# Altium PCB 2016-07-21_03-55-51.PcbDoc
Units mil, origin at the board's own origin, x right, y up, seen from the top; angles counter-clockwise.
Board outline 4250 x 2000 mil, 4 copper layers (Top Layer, MidLayer1, MidLayer2, Bottom Layer); 25 components, 16 nets, 65 pads, 67 vias.
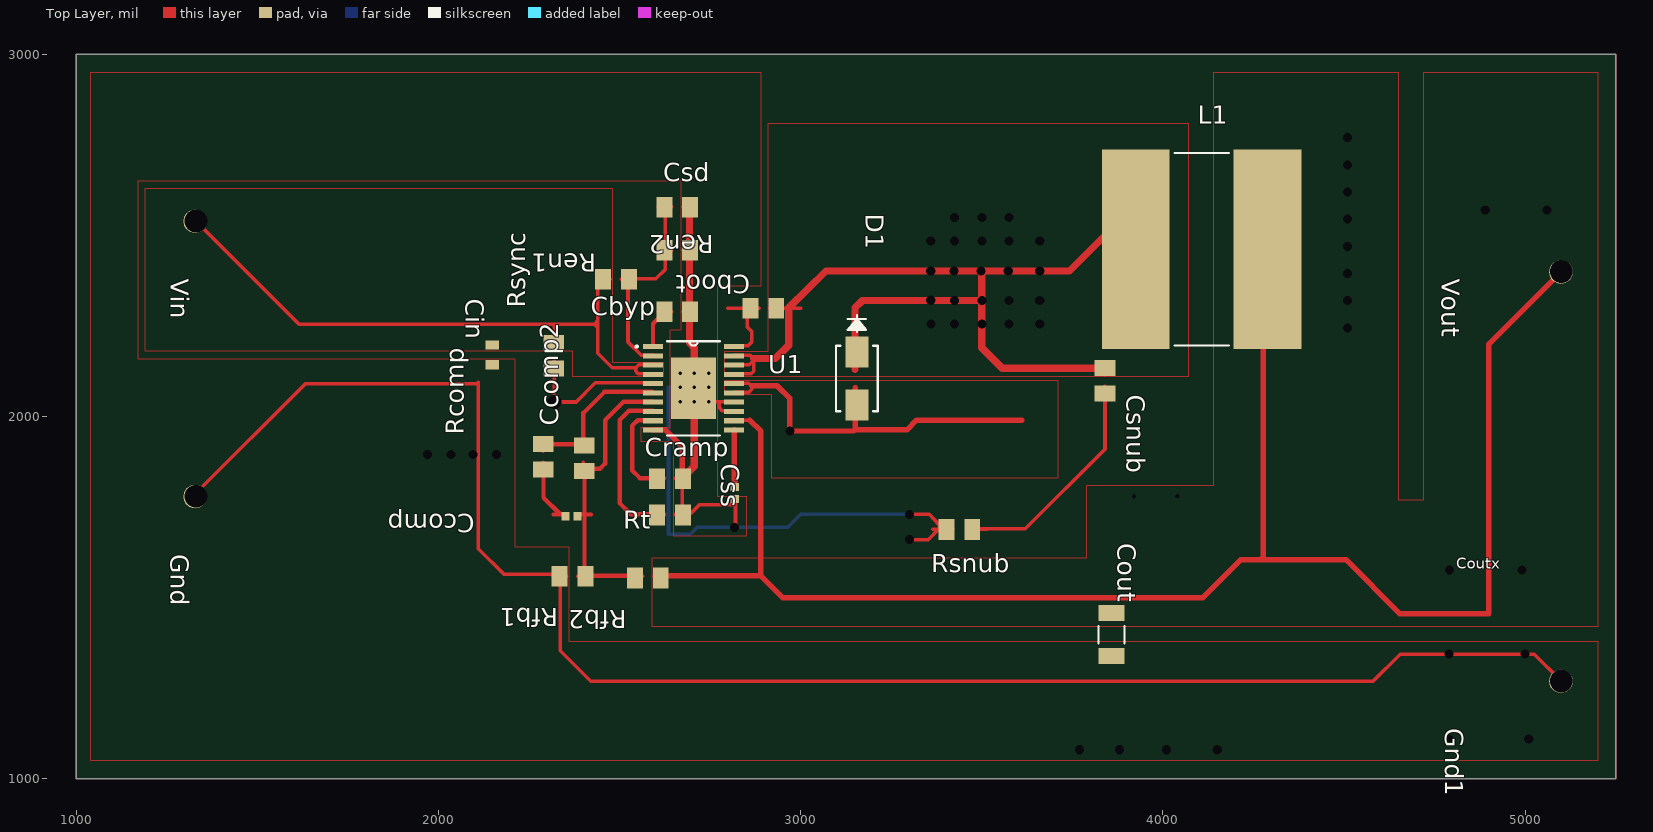
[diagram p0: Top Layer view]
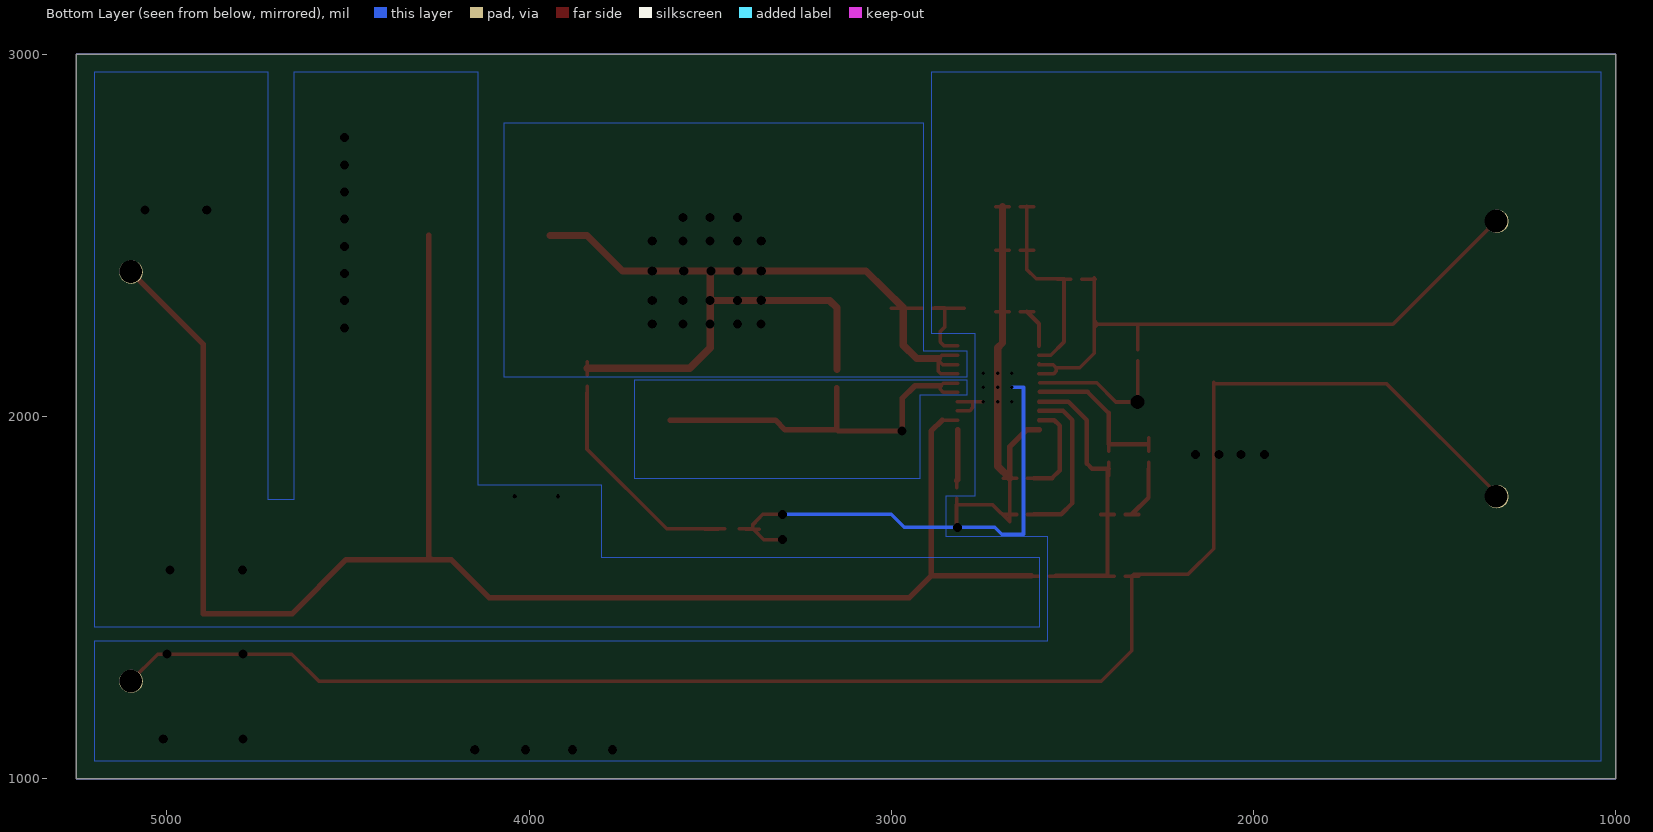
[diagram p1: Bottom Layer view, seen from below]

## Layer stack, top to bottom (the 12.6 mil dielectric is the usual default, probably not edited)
Top Layer: signal copper 1.4
Dielectric: core 12.6, FR-4, Dk 4.8
MidLayer1: signal copper 1.4
Dielectric: prepreg 12.6, FR-4, Dk 4.8
MidLayer2: signal copper 1.4
Dielectric: core 12.6, FR-4, Dk 4.8
Bottom Layer: signal copper 1.4

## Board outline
1000,1000 5250,1000 5250,3000 1000,3000

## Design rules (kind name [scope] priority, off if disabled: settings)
PlaneConnect [All] p0: scope1count=1 scope1_0_kind=Board scope1_0_value=Board scope2count=1 scope2_0_kind=Board scope2_0_value=Board commentlength=0 planeconnectstyle=Direct reliefexpansion=20 reliefentries=4 reliefconductorwidth=10 reliefairgap=10
PlaneConnect [All] p1: planeconnectstyle=Direct reliefexpansion=20 reliefentries=4 reliefconductorwidth=10 reliefairgap=10
PolygonConnect [All] p0: scope1count=1 scope1_0_kind=Board scope1_0_value=Board scope2count=1 scope2_0_kind=Board scope2_0_value=Board commentlength=0 connectstyle=Direct reliefconductorwidth=10 reliefentries=4 polygonreliefangle="90 Angle"
PolygonConnect [All] p1: connectstyle=Direct reliefconductorwidth=10 reliefentries=4 polygonreliefangle="90 Angle"

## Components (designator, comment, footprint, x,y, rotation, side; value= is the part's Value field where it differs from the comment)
Cboot "" 0805 2897,2299 r180 top
Cbyp "" 0805 2659,2289 r0 top
Ccomp "" 0402 2367,1725 r180 top
Ccomp2 "" 0805 2402,1885 r90 top
Cin "" 0603 2148,2170 r270 top
Cout "" 1206_190 3858,1398 r270 top
Cramp "" 0805 2639,1828 r0 top
Csd "" 0805 2659,2578 r0 top
Csnub "" 0805 3840,2099 r270 top
Css "" 0402 2818,1789 r270 top
D1 "" SMA 3155,2105 r270 top
Gnd "" TP-1502 1328,1779 r270 top
Gnd1 "" TP-1502 5099,1269 r270 top
L1 "" SDR1307 4107,2462 r0 top
Rcomp "" 0805 2289,1889 r90 top
Ren1 "" 0805 2490,2379 r180 top
Ren2 "" 0805 2659,2459 r180 top
Rfb1 "" 0805 2370,1559 r180 top
Rfb2 "" 0805 2578,1554 r180 top
Rsnub "" 0805 3438,1688 r0 top
Rsync "" 0805 2318,2168 r90 top
Rt "" 0805 2639,1728 r0 top
U1 "" MXA20A 2704,2078 r0 top
Vin "" TP-1502 1328,2539 r270 top
Vout "" TP-1502 5099,2399 r270 top

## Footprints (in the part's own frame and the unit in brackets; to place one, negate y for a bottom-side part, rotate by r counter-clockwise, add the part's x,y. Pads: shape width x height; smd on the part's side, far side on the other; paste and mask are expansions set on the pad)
0402 [mil]
  rect 22x24 smd: 1(-16.5,0) 2(16.5,0)
0603 [mil]
  rect 26x38 smd: 1(-27.5,0) 2(27.5,0)
0805 [mil]
  rect 44x57 smd: 1(-35.5,0) 2(35.5,0)
1206_190 [mil]
  rect 44x71 smd: 1(-59,0) 2(59,0)
  silkscreen extent -24,-36 24,36
MXA20A [mil]
  rect 56x14 smd: 1(-112,115.16) 2(-112,89.57) 3(-112,63.98) 4(-112,38.39) 5(-112,12.8) 6(-112,-12.8) 7(-112,-38.39) 8(-112,-63.98) 9(-112,-89.57) 10(-112,-115.16) 11(112,-115.16) 12(112,-89.57) 13(112,-63.98) 14(112,-38.39) 15(112,-12.8) 16(112,12.8) 17(112,38.39) 18(112,63.98) 19(112,89.57) 20(112,115.16)
  rect 124x171 smd: 21(0,0)
  silkscreen extent -160,-130 74,130
SDR1307 [mil]
  rect 187x551 smd: 1(-182,0) 2(182,0)
  silkscreen extent -75,-266 75,266
SMA [mil]
  rect 86x64 smd: 1(-73,0) 2(73,0)
  silkscreen extent -174,-58 91,58
TP-1502 [mil]
  round 65 / inner round 0 / far side round 65 hole 32: 1(0,0)

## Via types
v1: diameter 0, hole 25, Top Layer to Bottom Layer, 51 vias
v2: diameter 0, hole 10, Top Layer to Bottom Layer, 9 vias
v3: diameter 0, hole 63, Top Layer to Bottom Layer, 4 vias
v4: diameter 0, hole 12, Top Layer to Bottom Layer, 2 vias
v5: diameter 0, hole 38, Top Layer to Bottom Layer, 1 vias

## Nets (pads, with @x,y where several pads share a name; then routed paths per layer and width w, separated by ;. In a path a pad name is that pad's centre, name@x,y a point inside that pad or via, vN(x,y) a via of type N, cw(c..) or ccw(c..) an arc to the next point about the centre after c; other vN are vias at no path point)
0: Cbyp.2 Cin.2 Cout.2 Cramp.2 Csd.2 Css.2 Gnd1.1 Gnd.1 Ren2.1 Rfb1.2 Rsnub.1 Rt.2 U1.10 U1.13 U1.14 U1.21 | length 7788.8
  Top Layer w10: v3(1330,1780) 1330,1788 1632,2090 2105,2090 2110,2094 2110,1635 2180,1565 Rfb1.2@2331,1565 ; Rfb1.2@2317,1559.5 Rfb1.2@2354,1559.5 ; Rfb1.2@2336,1560 2336,1353 2420,1269 4580,1269 4655,1344 v1(4790,1344) 4900,1344 5025,1344 v3(5100,1270) ; Rt.2@2654,1729.5 Rt.2@2691,1729.5 ; Cramp.2@2654,1829.5 Cramp.2@2691,1829.5 ; Cramp.2@2673,1830 2673,1710 2720,1756 2820,1756 2820,1697 v1(2817,1694) ; Cbyp.2@2674,2289.5 Cbyp.2@2711,2289.5 ; Ren2.1@2674,2459.5 Ren2.1@2711,2459.5 ; Csd.2@2674,2579.5 Csd.2@2711,2579.5 ; v2(2746,2041) 2775,2041 ; U1.13@2817,2016 2783,2016 2775,2025 2775,2041 ; U1.14@2817,2041 2775,2041 ; 2819.5,1737 Css.2@2819.5,1774 ; v1(3300,1660) 3352,1660 Rsnub.1@3382,1690 ; v1(3300,1730) 3355,1730 3382,1702 Rsnub.1@3382,1690 ; 3364,1689 Rsnub.1@3401,1689 ; Rsnub.1@3420,1690 Rsnub.1@3382,1690
  Top Layer w15: U1.10@2592,1964 2625,1964 2673,1916 Cramp.2@2673,1830
  Top Layer w20: Cramp.2@2673,1830 2706,1863 v2(2706,2041) v2(2706,2081) v2(2706,2120) 2706,2190 2693,2203 2693,2290 2693,2460 Csd.2@2693,2580
  Bottom Layer w10: v2(2667,2081) 2635,2081 2635,1675 2695,1675 2714,1694 v1(2817,1694) 2964,1694 3000,1730 v1(3300,1730)
  other v1: 3770,1080 3880,1080 4010,1080 4150,1080 4790,1110 5010,1110 5000,1344 1970,1895 2035,1895 2095,1895 2160,1895
  other v2: 2667,2041 2746,2081 2667,2120 2746,2120
1: Css.1 U1.11 | length 179.2
  Top Layer w10: Css.1@2819.5,1804 2819.5,1841
  Top Layer w15: U1.11@2817,1964 2817,1826 2820,1823
2: Cbyp.1 U1.1 | length 146.1
  Top Layer w10: Cbyp.1@2607,2289.5 Cbyp.1@2644,2289.5
  Top Layer w12: U1.1@2592,2195 2592,2256 Cbyp.1@2626,2290
3: Cramp.1 U1.9 | length 303.9
  Top Layer w10: Cramp.1@2587,1829.5 Cramp.1@2624,1829.5
  Top Layer w12: U1.9@2592,1990 2550,1990 2535,1975 2535,1851 2556,1830 Cramp.1@2606,1830
4: Rt.1 U1.8 | length 487.6
  Top Layer w10: Rt.1@2587,1729.5 Rt.1@2624,1729.5
  Top Layer w12: U1.8@2592,2016 2526,2016 2500,1990 2500,1761 2531,1730 Rt.1@2606,1730
5: Ccomp2.2 Rcomp.2 U1.6 | length 485
  Top Layer w10: Rcomp.2@2289.5,1904 Rcomp.2@2289.5,1941 ; Ccomp2.2@2399.5,1904 Ccomp2.2@2399.5,1941
  Top Layer w12: Rcomp.2@2290,1923 2400,1923 2400,2010 2458,2068 U1.6@2590,2068
6: Ccomp2.1 Ccomp.1 Rfb1.1 Rfb2.2 U1.7 | length 927.2
  Top Layer w10: Rfb1.1@2384,1559.5 Rfb1.1@2421,1559.5 ; Ccomp.1@2384,1729.5 2421,1729.5 ; Ccomp2.1@2399.5,1837 2399.5,1874 ; Rfb2.2@2527,1559.5 Rfb2.2@2564,1559.5
  Top Layer w12: Rfb2.2@2546,1560 2403,1560 2403,1730 2403,1853 2400,1856 2446,1856 2460,1870 2460,1990 2511,2041 U1.7@2592,2041
7: Cboot.1 Csnub.1 D1.1 L1.1 U1.17 U1.18 U1.19 | length 2706.6
  Top Layer w10: U1.17@2817,2118 2863,2118 2870,2125 2870,2155 ; U1.18@2817,2143 2858,2143 2870,2155 ; U1.19@2817,2169 2860,2169 2870,2160 2870,2155 ; Cboot.1@2914,2299 3000,2299 ; Csnub.1@3839.5,2114 Csnub.1@3839.5,2151
  Top Layer w20: 2870,2160 2930,2160 2967,2197 2967,2300 3070,2402 v1(3359,2402) v1(3423,2402) v1(3498,2402) ; 3150,2130 3150,2236 3150,2300 3170,2320 v1(3425,2320) v1(3500,2320) ; Csnub.1@3840,2133 3556,2133 3500,2190 v1(3500,2255) v1(3500,2320) ; L1.1@3942,2500 3840,2500 3742,2402 v1(3660,2402) v1(3573,2402) v1(3498,2402) ; v1(3498,2402) 3500,2401 v1(3500,2320)
  other v1: 3360,2255 3425,2255 3575,2255 3660,2255 3575,2320 3660,2320 3359,2321 3359,2485 3425,2485 3500,2485 3575,2485 3660,2485 3425,2550 3500,2550 3575,2550
8: D1.2 U1.15 U1.16 | length 1090.3
  Top Layer w10: U1.15@2817,2067 2857,2067 2865,2075 2865,2085 2857,2092 U1.16@2817,2092
  Top Layer w15: 2865,2085 2934,2085 2970,2050 v1(2970,1960) 3146,1960 3150,1963 ; 3150,2080 3150,1963 ; 3610,1990 3410,1990 3320,1990 3293,1963 3150,1963
9: Cin.1 Ren1.2 Rsync.2 U1.3 U1.4 Vin.1 | length 1825.7
  Top Layer w10: v3(1330,2540) 1615,2255 2109,2255 2110,2255 2320,2255 ; Rsync.2@2319.5,2184 Rsync.2@2319.5,2221 ; Rsync.2@2320,2203 2320,2255 ; Ren1.2@2437,2379.5 Ren1.2@2474,2379.5 ; Ren1.2@2440,2383 2440,2265 ; U1.3@2591,2145 U1.3@2592,2143 ; U1.4@2592,2118 2551,2118 2545,2125 2545,2135 ; U1.3@2593,2143 U1.3@2592,2143 ; 2320,2255 2430,2255 ; 2430,2255 2440,2245 ; 2430,2255 2440,2255 ; 2430,2255 2440,2265 ; 2440,2245 2440,2175 2480,2135 2545,2135 ; 2440,2245 2440,2255 ; 2440,2255 2440,2265 ; 2545,2135 2553,2143 U1.3@2592,2143
10: Cout.1 L1.2 Rfb2.1 U1.12 Vout.1 | length 4865.7
  Top Layer w10: Rfb2.1@2594,1559.5 Rfb2.1@2631,1559.5 ; U1.12@2817,1990 2859,1990
  Top Layer w15: Rfb2.1@2613,1560 2890,1560 ; 2859,1990 2890,1960 2890,1560 ; L1.2@4277,2500 4277,1612 4270,1605 ; v3(5100,2400) 4900,2200 4900,1455 4654,1455 4505,1605 4270,1605 ; 2890,1560 2950,1500 4110,1500 4215,1605 4270,1605
  other v1: 4791,1576 4991,1576 4510,2245 4510,2320 4510,2395 4510,2470 4510,2545 4890,2570 5060,2570 4510,2620 4510,2695 4510,2770
  other v4: 3920,1780 4040,1780
11: Cboot.2 U1.20 | length 266.2
  Top Layer w10: 2799,2299 2885,2299 ; U1.20@2817,2195 2854,2195 2865,2206 2865,2235 2852,2247 2852,2300 Cboot.2@2880,2300
12: Ccomp.2 Rcomp.1 | length 219.1
  Top Layer w10: Rcomp.1@2289.5,1837 Rcomp.1@2289.5,1874 ; 2317,1729.5 Ccomp.2@2354,1729.5
  Top Layer w12: Rcomp.1@2290,1856 2290,1776 2336,1730
13: Csnub.2 Rsnub.2 | length 701.1
  Top Layer w10: Rsnub.2@3460,1690 3497,1690 3620,1690 3840,1910 Csnub.2@3840,2066 ; Rsnub.2@3478,1689 3515,1689 ; Csnub.2@3839.5,2047 Csnub.2@3839.5,2084
24: Rsync.1 U1.5 | length 425
  Top Layer w10: Rsync.1@2319.5,2117 Rsync.1@2319.5,2154 ; Rsync.1@2320,2136 v5(2320,2040) 2380,2040 2433,2093 U1.5@2590,2093
26: Csd.1 Ren1.1 Ren2.2 U1.2 | length 657.1
  Top Layer w10: Ren1.1@2504,2379.5 Ren1.1@2541,2379.5 ; U1.2@2592,2169 2560,2169 2523,2206 2523,2380 2600,2380 2626,2406 2626,2460 Csd.1@2626,2580 ; Ren2.2@2607,2459.5 Ren2.2@2644,2459.5 ; Csd.1@2607,2579.5 Csd.1@2644,2579.5

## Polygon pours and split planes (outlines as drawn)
10 on Top Layer " " (solid, pour order 0): 2590,1420 2590,1610 3790,1610 3790,1810 4140,1810 4140,2950 4650,2950 4650,1770 4720,1770 4720,2950 5200,2950 5200,1420
9 on Top Layer " " (solid, pour order 1): 1190,2180 1190,2630 2480,2630 2480,2150 2620,2150 2620,2110 2370,2110 2370,2180
8 on Top Layer " " (solid, pour order 2): 2790,2100 3710,2100 3710,1830 2920,1830 2920,2060 2790,2060
7 on Top Layer " " (solid, pour order 3): 2790,2180 2910,2180 2910,2810 4070,2810 4070,2110 2790,2110
0 on Top Layer " " (solid, pour order 7): 2210,2160 2210,1640 2360,1640 2360,1380 5200,1380 5200,1050 1040,1050 1040,2950 2890,2950 2890,2360 2770,2360 2770,1780 2850,1780 2850,1670 2650,1670 2650,1930 2560,1930 2560,1970 2640,1970 2640,2240 2670,2240 2670,2650 1170,2650 1170,2160
10 on Bottom Layer " " (solid, pour order 4): 2590,1420 2590,1610 3800,1610 3800,1810 4140,1810 4140,2950 4650,2950 4650,1770 4720,1770 4720,2950 5200,2950 5200,1420
8 on Bottom Layer " " (solid, pour order 5): 2790,2100 3710,2100 3710,1830 2920,1830 2920,2060 2790,2060
7 on Bottom Layer " " (solid, pour order 6): 2790,2180 2910,2180 2910,2810 4070,2810 4070,2110 2790,2110
0 on Bottom Layer " " (solid, pour order 8): 2890,2950 2890,2230 2770,2230 2770,1780 2850,1780 2850,1670 2570,1670 2570,1380 5200,1380 5200,1050 1040,1050 1040,2950

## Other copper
Multi-Layer:
  the board outline again, w1

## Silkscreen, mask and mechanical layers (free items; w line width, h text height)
Top Overlay:
  text "Coutx" at 4810,1580 h30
